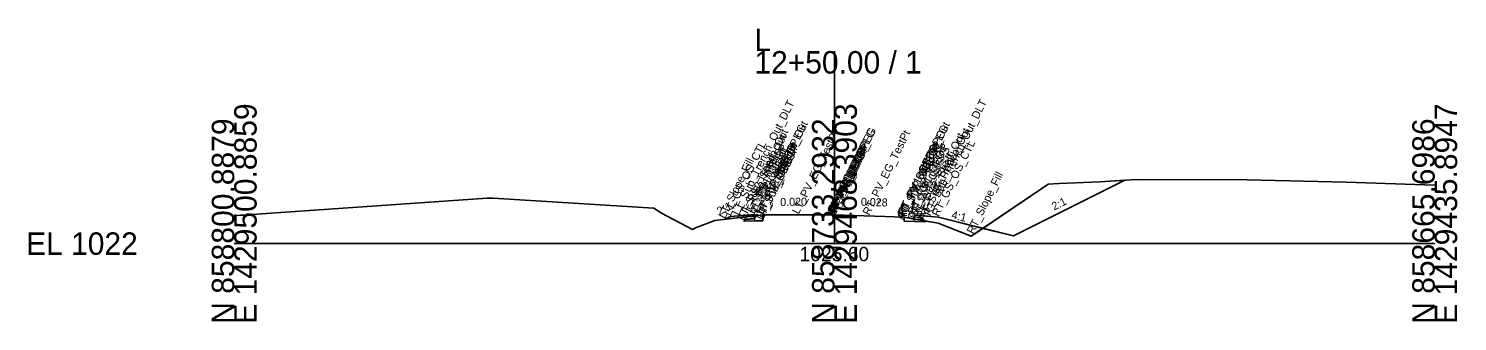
# Model space of a CAD drawing. Extents: x -26 to 176, y -10 to 13058.
# Drawn here: x -25.7 to 152.8, y 1990.3 to 2026.8 of the extents above; entities that cross this region are included whole.
import ezdxf

# ---------------------------------------------------------------- set-up
doc = ezdxf.new("R2010")
doc.units = 0
for name, color, linetype in [('Default', 7, 'Continuous'), ('Exist Cross Section Cell', 7, 'Continuous'), ('Exist XS Center Line Elevation Label', 7, 'Continuous'), ('Exist XS Ground Line', 7, 'Continuous'), ('Old_Level_50', 7, 'Continuous'), ('Prop CMT Pvmt Course 1', 7, 'Continuous'), ('Prop CMT Pvmt Course 2', 7, 'Continuous'), ('Prop CMT Pvmt Surface Shoulder', 7, 'Continuous'), ('Prop CMT Pvmt Wedge Surface 1', 7, 'Continuous'), ('Prop CMT Pvmt Wedge Surface 2', 7, 'Continuous'), ('Prop CMT Shld Paved Course 1', 7, 'Continuous'), ('Prop CMT Shld Paved Course 2', 7, 'Continuous'), ('Prop CMT Slope Grass', 7, 'Continuous'), ('Prop CMT Subgrade Earthwork', 7, 'Continuous'), ('Prop XS Dump Level', 7, 'Continuous'), ('Prop XS SE Text', 7, 'Continuous'), ('Prop XS Side Slope Text', 7, 'Continuous')]:
    doc.layers.add(name, color=color, linetype=linetype)

msp = doc.modelspace()

# ---------------------------------------------------------------- linework, layer by layer
at = {"layer": 'Exist Cross Section Cell'}
for p, q in [((75, 2000), (75, 2024)), ((0, 2000), (75, 2000)), ((75, 2000), (150, 2000))]:
    msp.add_line(p, q, dxfattribs=at)
at = {"layer": 'Exist XS Ground Line'}
msp.add_lwpolyline([(0, 2003.48), (0.77, 2003.54), (1.21, 2003.56), (1.64, 2003.58), (17.83, 2004.7), (31.6, 2005.65), (32.36, 2005.65), (52.42, 2004.43), (53.37, 2003.81), (57.27, 2001.77), (57.64, 2001.96), (60.06, 2002.87), (61.13, 2003.01), (66.05, 2003.59), (72.3, 2003.6), (74.89, 2003.6), (81.28, 2003.38), (83.72, 2003.28), (87.95, 2002.54), (92.07, 2000.91), (100.93, 2006.89), (101.72, 2007.42), (103.09, 2007.5), (108.16, 2007.71), (112.69, 2008), (126.54, 2007.94), (138.94, 2007.68), (150, 2007.28)], dxfattribs=at)
at = {"layer": 'Old_Level_50'}
for points in [[(93.55, 2001.9), (97.36, 2000.95), (111.28, 2007.91), (108.16, 2007.71), (103.09, 2007.5), (101.72, 2007.42), (100.93, 2006.89)], [(93.55, 2001.9), (100.93, 2006.89), (101.72, 2007.42), (103.09, 2007.5), (108.16, 2007.71), (111.28, 2007.91), (97.36, 2000.95)], [(93.55, 2001.9), (100.93, 2006.89), (101.72, 2007.42), (103.09, 2007.5), (108.16, 2007.71), (111.28, 2007.91), (97.36, 2000.95)], [(65, 2003.61), (65, 2003.47), (61.33, 2003.03), (62, 2003.37)], [(65, 2003.61), (65, 2003.47), (61.33, 2003.03), (62, 2003.37)], [(65, 2003.61), (65, 2003.47), (61.33, 2003.03), (62, 2003.37)], [(63.95, 2003.05), (63.69, 2002.79), (65, 2002.82), (66.05, 2002.84), (66.07, 2003.59), (66.05, 2003.59), (65, 2003.47), (65, 2003.07), (64.45, 2003.06)], [(64.45, 2003.06), (63.95, 2003.05), (63.69, 2002.79), (65, 2002.82), (66.05, 2002.84), (66.07, 2003.59), (66.05, 2003.59), (65, 2003.47), (65, 2003.07)], [(64.45, 2003.06), (63.95, 2003.05), (63.69, 2002.79), (65, 2002.82), (66.05, 2002.84), (66.07, 2003.59), (66.05, 2003.59), (65, 2003.47), (65, 2003.07)], [(85.41, 2002.98), (85, 2002.99), (85, 2003.05), (83.72, 2003.28), (83.7, 2003.28), (83.72, 2002.78), (85, 2002.74), (86.31, 2002.71), (86.17, 2002.85)], [(85.41, 2002.98), (85, 2002.99), (85, 2003.05), (83.72, 2003.28), (83.7, 2003.28), (83.72, 2002.78), (85, 2002.74), (86.31, 2002.71), (86.17, 2002.85)], [(85.41, 2002.98), (85, 2002.99), (85, 2003.05), (83.72, 2003.28), (83.7, 2003.28), (83.72, 2002.78), (85, 2002.74), (86.31, 2002.71), (86.17, 2002.85)], [(86.05, 2002.97), (86.17, 2002.85), (87.95, 2002.54), (92.07, 2000.91), (93.55, 2001.9), (88, 2003.29), (85, 2003.53), (85, 2003.05), (85.41, 2002.98), (85.55, 2002.98)], [(85, 2003.05), (85.41, 2002.98), (85.55, 2002.98), (86.05, 2002.97), (86.17, 2002.85), (87.95, 2002.54), (92.07, 2000.91), (93.55, 2001.9), (88, 2003.29), (85, 2003.53)], [(85, 2003.05), (85.41, 2002.98), (85.55, 2002.98), (86.05, 2002.97), (86.17, 2002.85), (87.95, 2002.54), (92.07, 2000.91), (93.55, 2001.9), (88, 2003.29), (85, 2003.53)], [(85.41, 2002.98), (85, 2002.99), (85, 2003.05)], [(85.41, 2002.98), (85, 2002.99), (85, 2003.05)], [(85.41, 2002.98), (85, 2002.99), (85, 2003.05)]]:
    msp.add_lwpolyline(points, close=True, dxfattribs=at)
at = {"layer": 'Prop CMT Pvmt Course 1'}
for points in [[(65, 2003.61), (65, 2003.07)], [(85, 2003.53), (85, 2002.99)]]:
    msp.add_lwpolyline(points, dxfattribs=at)
at = {"layer": 'Prop CMT Pvmt Course 2'}
for points in [[(65, 2002.82), (66.05, 2002.84)], [(85, 2002.74), (83.72, 2002.78)]]:
    msp.add_lwpolyline(points, dxfattribs=at)
at = {"layer": 'Prop CMT Pvmt Surface Shoulder'}
for points in [[(65, 2003.61), (65, 2003.61)], [(85, 2003.53), (85, 2003.53)]]:
    msp.add_lwpolyline(points, dxfattribs=at)
at = {"layer": 'Prop CMT Pvmt Wedge Surface 1'}
for points in [[(65, 2003.07), (65, 2003.61)], [(85, 2002.99), (85, 2003.53)]]:
    msp.add_lwpolyline(points, dxfattribs=at)
at = {"layer": 'Prop CMT Pvmt Wedge Surface 2'}
for points in [[(65, 2003.07), (65, 2003.61)], [(85, 2002.99), (85, 2003.53)]]:
    msp.add_lwpolyline(points, dxfattribs=at)
at = {"layer": 'Prop CMT Shld Paved Course 1'}
for points in [[(65, 2003.61), (65, 2003.61)], [(65, 2003.07), (65, 2003.61)], [(85, 2003.53), (85, 2003.53)], [(85, 2002.99), (85, 2003.53)], [(64.45, 2003.06), (65, 2003.07)], [(85.55, 2002.98), (85, 2002.99)]]:
    msp.add_lwpolyline(points, dxfattribs=at)
at = {"layer": 'Prop CMT Shld Paved Course 2'}
for points in [[(65, 2003.07), (64.45, 2003.06), (63.95, 2003.05), (63.69, 2002.79)], [(63.69, 2002.79), (65, 2002.82)], [(85, 2002.99), (85.55, 2002.98), (86.05, 2002.97), (86.31, 2002.71)], [(86.31, 2002.71), (85, 2002.74)]]:
    msp.add_lwpolyline(points, dxfattribs=at)
at = {"layer": 'Prop CMT Slope Grass'}
for p, q in [((97.36, 2000.95), (111.28, 2007.91)), ((88, 2003.29), (97.36, 2000.95))]:
    msp.add_line(p, q, dxfattribs=at)
for points in [[(65, 2003.61), (62, 2003.37), (61.33, 2003.03)], [(85, 2003.53), (88, 2003.29)]]:
    msp.add_lwpolyline(points, dxfattribs=at)
at = {"layer": 'Prop CMT Subgrade Earthwork'}
for points in [[(66.05, 2002.84), (66.07, 2003.59)], [(83.72, 2002.78), (83.7, 2003.28)], [(65, 2002.82), (63.69, 2002.79)], [(66.05, 2002.84), (65, 2002.82)], [(83.72, 2002.78), (85, 2002.74)], [(85, 2002.74), (86.31, 2002.71)]]:
    msp.add_lwpolyline(points, dxfattribs=at)

# ---------------------------------------------------------------- texts
at = {"layer": 'Default'}
msp.add_text('-', height=0.0001, dxfattribs=at).set_placement((0, 2000))
at = {"layer": 'Exist Cross Section Cell'}
for s, p in [('L', (65, 2024)), ('12+50.00 / 1', (65, 2021.2)), ('EL 1022', (-26, 1998.6))]:
    msp.add_text(s, height=2.8, dxfattribs=at).set_placement(p)
for s, p in [('E 1429500.8859', (2.8, 1990)), ('E 1429468.3903', (77.8, 1990)), ('E 1429435.8947', (152.8, 1990)), ('N 858800.8879', (0, 1990)), ('N 858733.2932', (75, 1990)), ('N 858665.6986', (150, 1990))]:
    msp.add_text(s, height=2.8, rotation=90, dxfattribs=at).set_placement(p)
at = {"layer": 'Exist XS Center Line Elevation Label'}
msp.add_text('1025.60', height=1.8, dxfattribs=at).set_placement((70.64, 1997.8))
msp.add_text('1025.60', height=1.8, dxfattribs=at).set_placement((70.64, 1997.8))
msp.add_text('1025.60', height=1.8, dxfattribs=at).set_placement((70.64, 1997.8))
at = {"layer": 'Prop XS Dump Level'}
for s, p in [('LT_Sub_Trench_Out_DLT', (63.03, 2003.45)), ('RT_Sub_Trench_Out_DLT', (86.97, 2003.37)), ('LT_Sub_Trench_Out', (63.69, 2002.79)), ('LT_PV_OEEOP_EG', (66.05, 2003.59)), ('LT_PV_Sub_Tie_Out', (66.07, 2003.59)), ('LT_PV_EG_TestPt', (70.53, 2003.6)), ('RT_PV_IEEOP_EG', (75, 2003.6)), ('LT_PV_IEEOP_EG', (75, 2003.6)), ('RT_PV_EG_TestPt', (79.36, 2003.44)), ('RT_PV_Sub_Tie_Out', (83.7, 2003.28)), ('RT_PV_OEEOP_EG', (83.72, 2003.28)), ('RT_Sub_Trench_Out', (86.31, 2002.71)), ('LT_GS_OS_CTL', (62, 2003.37)), ('LT_PS2_Shelf_Out', (63.95, 2003.05)), ('LT_PV1_OEOT', (65, 2003.61)), ('LT_PS1_OEOP', (65, 2003.61)), ('LT_PV1_OEEOP', (66.05, 2003.51)), ('LT_PV2_OEEOP', (66.05, 2003.09)), ('LT_Sub_OEEOP', (66.05, 2002.84)), ('RT_PV1_IEEOP', (75, 2003.69)), ('LT_PV1_IEEOP', (75, 2003.69)), ('RT_PV2_IEEOP', (75, 2003.27)), ('LT_PV2_IEEOP', (75, 2003.27)), ('RT_PV1_OEEOP', (83.72, 2003.44)), ('RT_PV2_OEEOP', (83.72, 2003.03)), ('RT_Sub_OEEOP', (83.72, 2002.78)), ('RT_PV1_OEOT', (85, 2003.53)), ('RT_PS1_OEOP', (85, 2003.53)), ('RT_PS2_Shelf_Out', (86.05, 2002.97)), ('RT_GS_OS_CTL', (88, 2003.29)), ('LT_Slope_Fill', (61.33, 2003.03)), ('LT_PS2_OEOP', (64.45, 2003.06)), ('LT_PV2_OEOT', (65, 2003.07)), ('LT_Sub_OEOT', (65, 2002.82)), ('RT_PV2_OEOT', (85, 2002.99)), ('RT_Sub_OEOT', (85, 2002.74)), ('RT_PS2_OEOP', (85.55, 2002.98)), ('PV1_PGL', (75, 2003.81)), ('PV2_PGL', (75, 2003.27)), ('RT_Slope_Fill', (92.37, 2001.11))]:
    msp.add_text(s, height=1, rotation=63.5833, dxfattribs=at).set_placement(p)
at = {"layer": 'Prop XS SE Text'}
for s, rotation, p in [('0.020', 1.1458, (68.23, 2004.68)), ('0.028', 358.3961, (78.29, 2004.72))]:
    msp.add_text(s, height=1, rotation=rotation, dxfattribs=at).set_placement(p)
at = {"layer": 'Prop XS Side Slope Text'}
for s, rotation, p in [('2:1', 26.565, (60.62, 2003.52)), ('2:1', 26.5651, (102.45, 2004.11)), ('4:1', 345.9638, (89.55, 2003.16))]:
    msp.add_text(s, height=1, rotation=rotation, dxfattribs=at).set_placement(p)

doc.saveas('drawing.dxf')
